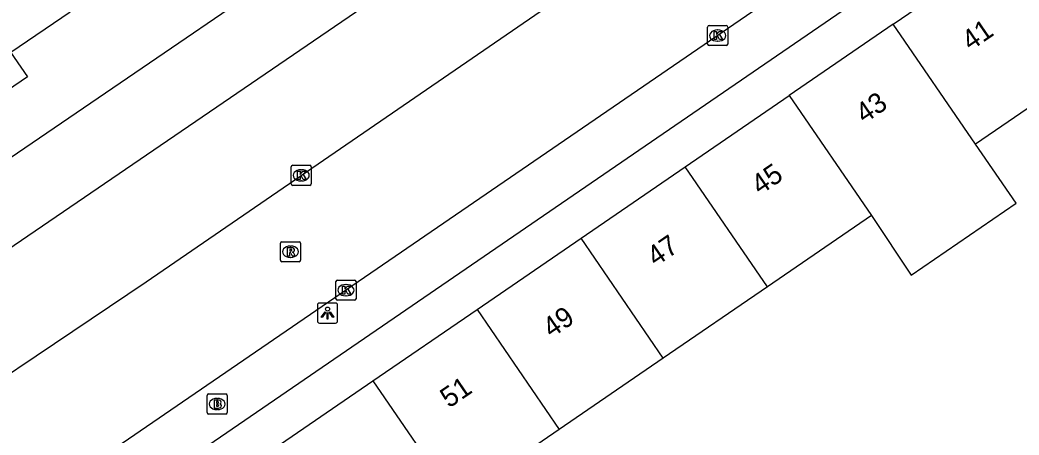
# Model space of a CAD drawing. Extents: x 157466 to 158888, y 383063 to 384677.
# Drawn here: x 158400.94 to 158450.69, y 383765.41 to 383786.08 of the extents above; entities that cross this region are included whole.
import ezdxf

# ---------------------------------------------------------------- set-up
doc = ezdxf.new("R2010")
doc.units = 0
for name, color, linetype in [('IMGEO_Brandkraan', 7, 'Continuous'), ('IMGEO_Kolk', 7, 'Continuous'), ('IMGEO_Lichtpunt', 7, 'Continuous'), ('IMGEO_Pand', 7, 'Continuous'), ('IMGEO_Pand_nummerreeks', 7, 'Continuous'), ('IMGEO_Rijbaan_lokaal_open', 7, 'Continuous'), ('IMGEO_Rioolput', 7, 'Continuous'), ('IMGEO_Voetpad_open', 7, 'Continuous')]:
    doc.layers.add(name, color=color, linetype=linetype)

msp = doc.modelspace()

# ---------------------------------------------------------------- linework, layer by layer
at = {"layer": 'IMGEO_Brandkraan'}
for p, q in [((158410.262, 383766.531), (158410.262, 383767.383)), ((158410.337, 383767.457), (158411.189, 383767.457)), ((158410.75, 383767.237), (158410.775, 383767.237)), ((158411.263, 383767.383), (158411.263, 383766.531)), ((158410.773, 383766.677), (158410.748, 383766.677)), ((158411.189, 383766.457), (158410.337, 383766.457))]:
    msp.add_line(p, q, dxfattribs=at)
for points in [[(158410.262, 383766.531), (158410.262, 383767.383)], [(158410.337, 383767.457), (158411.189, 383767.457)], [(158410.61, 383767.157), (158410.61, 383766.757), (158410.823, 383766.757)], [(158410.841, 383767.157), (158410.61, 383767.157)], [(158410.789, 383767.076), (158410.735, 383767.076), (158410.735, 383767)], [(158410.735, 383767), (158410.788, 383767)], [(158411.263, 383767.383), (158411.263, 383766.531)], [(158410.797, 383766.924), (158410.735, 383766.924), (158410.735, 383766.843)], [(158410.735, 383766.843), (158410.797, 383766.843)], [(158411.189, 383766.457), (158410.337, 383766.457)]]:
    msp.add_lwpolyline(points, dxfattribs=at)
for centre, radius, start, end in [((158410.339, 383767.381), 0.0765, 91.552, 178.448), ((158410.339, 383767.381), 0.0765, 91.552, 178.448), ((158410.79, 383767.038), 0.0379, 267.8285, 90.9355), ((158410.845, 383767.012), 0.145, 59.4692, 91.5367), ((158410.87, 383767.059), 0.0922, 285.5137, 58.1501), ((158411.187, 383767.381), 0.0765, 1.552, 88.448), ((158411.187, 383767.381), 0.0765, 1.552, 88.448), ((158410.339, 383766.533), 0.0765, 181.552, 268.448), ((158410.339, 383766.533), 0.0765, 181.552, 268.448), ((158410.798, 383766.883), 0.0404, 269.8759, 90.5077), ((158410.829, 383767.008), 0.251, 268.6676, 293.5347), ((158410.875, 383766.867), 0.105, 301.3115, 78.989), ((158411.187, 383766.533), 0.0765, 271.552, 358.448), ((158411.187, 383766.533), 0.0765, 271.552, 358.448)]:
    msp.add_arc(centre, radius, start, end, dxfattribs=at)
for centre, major_axis, ratio, start_param, end_param in [((158410.749, 383766.957), (-0.387, 0.002), 0.722429, 4.712389, 7.853982), ((158410.774, 383766.957), (-0.39, 0.002), 0.717154, 1.570796, 4.712389)]:
    msp.add_ellipse(centre, major_axis=major_axis, ratio=ratio, start_param=start_param, end_param=end_param, dxfattribs=at)
at = {"layer": 'IMGEO_Kolk'}
for p, q in [((158435.185, 383784.881), (158435.185, 383785.733)), ((158435.26, 383785.807), (158436.112, 383785.807)), ((158435.673, 383785.587), (158435.698, 383785.587)), ((158436.186, 383785.733), (158436.186, 383784.881)), ((158435.696, 383785.027), (158435.671, 383785.027)), ((158436.112, 383784.807), (158435.26, 383784.807)), ((158414.448, 383777.92), (158414.448, 383778.772)), ((158414.523, 383778.846), (158415.375, 383778.846)), ((158414.936, 383778.626), (158414.961, 383778.626)), ((158415.449, 383778.772), (158415.449, 383777.92)), ((158414.959, 383778.066), (158414.934, 383778.066)), ((158415.375, 383777.846), (158414.523, 383777.846)), ((158416.676, 383772.202), (158416.676, 383773.054)), ((158416.751, 383773.128), (158417.603, 383773.128)), ((158417.677, 383773.054), (158417.677, 383772.202)), ((158417.164, 383772.908), (158417.189, 383772.908)), ((158417.603, 383772.128), (158416.751, 383772.128)), ((158417.187, 383772.348), (158417.162, 383772.348))]:
    msp.add_line(p, q, dxfattribs=at)
for points in [[(158435.185, 383784.881), (158435.185, 383785.733)], [(158435.26, 383785.807), (158436.112, 383785.807)], [(158435.506, 383785.507), (158435.629, 383785.507), (158435.629, 383785.356), (158435.759, 383785.507), (158435.923, 383785.507), (158435.777, 383785.356), (158435.93, 383785.107), (158435.778, 383785.107), (158435.693, 383785.271), (158435.629, 383785.204), (158435.629, 383785.107), (158435.506, 383785.107), (158435.506, 383785.507)], [(158436.186, 383785.733), (158436.186, 383784.881)], [(158436.112, 383784.807), (158435.26, 383784.807)], [(158414.448, 383777.92), (158414.448, 383778.772)], [(158414.523, 383778.846), (158415.375, 383778.846)], [(158414.769, 383778.546), (158414.892, 383778.546), (158414.892, 383778.395), (158415.022, 383778.546), (158415.186, 383778.546), (158415.04, 383778.395), (158415.193, 383778.146), (158415.041, 383778.146), (158414.956, 383778.31), (158414.892, 383778.243), (158414.892, 383778.146), (158414.769, 383778.146), (158414.769, 383778.546)], [(158415.449, 383778.772), (158415.449, 383777.92)], [(158415.375, 383777.846), (158414.523, 383777.846)], [(158416.676, 383772.202), (158416.676, 383773.054)], [(158416.751, 383773.128), (158417.603, 383773.128)], [(158417.677, 383773.054), (158417.677, 383772.202)], [(158416.997, 383772.828), (158417.12, 383772.828), (158417.12, 383772.677), (158417.25, 383772.828), (158417.414, 383772.828), (158417.268, 383772.677), (158417.421, 383772.428), (158417.269, 383772.428), (158417.184, 383772.592), (158417.12, 383772.525), (158417.12, 383772.428), (158416.997, 383772.428), (158416.997, 383772.828)], [(158417.603, 383772.128), (158416.751, 383772.128)]]:
    msp.add_lwpolyline(points, dxfattribs=at)
for centre, start, end in [((158435.262, 383785.731), 91.552, 178.448), ((158435.262, 383785.731), 91.552, 178.448), ((158436.11, 383785.731), 1.552, 88.448), ((158436.11, 383785.731), 1.552, 88.448), ((158435.262, 383784.883), 181.552, 268.448), ((158435.262, 383784.883), 181.552, 268.448), ((158436.11, 383784.883), 271.552, 358.448), ((158436.11, 383784.883), 271.552, 358.448), ((158414.525, 383778.77), 91.552, 178.448), ((158414.525, 383778.77), 91.552, 178.448), ((158415.373, 383778.77), 1.552, 88.448), ((158415.373, 383778.77), 1.552, 88.448), ((158414.525, 383777.922), 181.552, 268.448), ((158414.525, 383777.922), 181.552, 268.448), ((158415.373, 383777.922), 271.552, 358.448), ((158415.373, 383777.922), 271.552, 358.448), ((158416.753, 383773.052), 91.552, 178.448), ((158416.753, 383773.052), 91.552, 178.448), ((158417.601, 383773.052), 1.552, 88.448), ((158417.601, 383773.052), 1.552, 88.448), ((158416.753, 383772.204), 181.552, 268.448), ((158416.753, 383772.204), 181.552, 268.448), ((158417.601, 383772.204), 271.552, 358.448), ((158417.601, 383772.204), 271.552, 358.448)]:
    msp.add_arc(centre, 0.0765, start, end, dxfattribs=at)
for centre, major_axis, ratio, start_param, end_param in [((158435.672, 383785.307), (-0.387, 0.002), 0.722429, 4.712389, 7.853982), ((158435.697, 383785.307), (-0.39, 0.002), 0.717154, 1.570796, 4.712389), ((158414.935, 383778.346), (-0.387, 0.002), 0.722429, 4.712389, 7.853982), ((158414.96, 383778.346), (-0.39, 0.002), 0.717154, 1.570796, 4.712389), ((158417.163, 383772.628), (-0.387, 0.002), 0.722429, 4.712389, 7.853982), ((158417.188, 383772.628), (-0.39, 0.002), 0.717154, 1.570796, 4.712389)]:
    msp.add_ellipse(centre, major_axis=major_axis, ratio=ratio, start_param=start_param, end_param=end_param, dxfattribs=at)
at = {"layer": 'IMGEO_Lichtpunt'}
for p, q in [((158416.661, 383771.984), (158415.853, 383771.984)), ((158416.661, 383771.984), (158415.853, 383771.984)), ((158415.759, 383771.889), (158415.759, 383771.082)), ((158415.759, 383771.889), (158415.759, 383771.082)), ((158416.755, 383771.082), (158416.755, 383771.889)), ((158416.755, 383771.082), (158416.755, 383771.889)), ((158415.853, 383770.988), (158416.661, 383770.988)), ((158415.853, 383770.988), (158416.661, 383770.988))]:
    msp.add_line(p, q, dxfattribs=at)
for points in [[(158416.133, 383771.553), (158416.172, 383771.525), (158415.984, 383771.263), (158415.946, 383771.29), (158416.133, 383771.553)], [(158416.235, 383771.505), (158416.282, 383771.505), (158416.282, 383771.183), (158416.235, 383771.183), (158416.235, 383771.505)], [(158416.345, 383771.525), (158416.383, 383771.552), (158416.57, 383771.29), (158416.531, 383771.262), (158416.345, 383771.525)]]:
    msp.add_lwpolyline(points, dxfattribs=at)
msp.add_circle((158416.258, 383771.687), 0.0994, dxfattribs=at)
for centre, start, end in [((158415.853, 383771.889), 90, 180), ((158415.853, 383771.889), 90, 180), ((158416.661, 383771.889), 0, 90), ((158416.661, 383771.889), 0, 90), ((158415.853, 383771.082), 180, 270), ((158415.853, 383771.082), 180, 270), ((158416.661, 383771.082), 270, 0), ((158416.661, 383771.082), 270, 360)]:
    msp.add_arc(centre, 0.0946, start, end, dxfattribs=at)
at = {"layer": 'IMGEO_Pand'}
for points in [[(158442.619, 383817.275), (158437.202, 383813.58), (158439.887, 383809.644), (158428.548, 383801.911), (158426.177, 383805.388), (158423.704, 383803.702), (158424.427, 383802.642), (158402.712, 383787.832), (158402.577, 383787.74), (158403.44, 383786.474), (158400.485, 383784.46), (158400.653, 383784.214), (158401.312, 383783.247), (158389.931, 383775.485), (158388.503, 383777.577), (158386.41, 383776.149), (158383.749, 383780.051)], [(158444.429, 383785.881), (158449.611, 383789.434)], [(158444.429, 383785.881), (158439.247, 383782.328)], [(158448.528, 383779.899), (158444.429, 383785.881)], [(158453.711, 383783.45), (158448.528, 383779.899)], [(158434.066, 383778.775), (158439.247, 383782.328)], [(158439.247, 383782.328), (158443.345, 383776.348)], [(158443.345, 383776.348), (158445.315, 383773.373), (158450.544, 383776.956), (158448.528, 383779.899)], [(158428.883, 383775.222), (158434.066, 383778.775)], [(158438.162, 383772.796), (158434.066, 383778.775)], [(158443.345, 383776.348), (158438.162, 383772.796)], [(158423.702, 383771.669), (158428.883, 383775.222)], [(158432.979, 383769.245), (158428.883, 383775.222)], [(158438.162, 383772.796), (158432.979, 383769.245)], [(158418.52, 383768.116), (158423.702, 383771.669)], [(158423.702, 383771.669), (158427.796, 383765.693)], [(158432.979, 383769.245), (158427.796, 383765.693)], [(158413.338, 383764.563), (158418.52, 383768.116)], [(158418.52, 383768.116), (158422.613, 383762.142)], [(158427.796, 383765.693), (158422.613, 383762.142)]]:
    msp.add_lwpolyline(points, dxfattribs=at)
at = {"layer": 'IMGEO_Rijbaan_lokaal_open'}
for points in [[(158394.384, 383764.411), (158407.233, 383773.047), (158444.242, 383798.459)], [(158447.639, 383793.508), (158438.021, 383786.908), (158394.268, 383756.934)]]:
    msp.add_lwpolyline(points, dxfattribs=at)
at = {"layer": 'IMGEO_Rioolput'}
for p, q in [((158413.915, 383774.116), (158413.915, 383774.968)), ((158413.99, 383775.042), (158414.842, 383775.042)), ((158414.916, 383774.968), (158414.916, 383774.116)), ((158414.403, 383774.822), (158414.428, 383774.822)), ((158414.842, 383774.042), (158413.99, 383774.042)), ((158414.426, 383774.262), (158414.401, 383774.262))]:
    msp.add_line(p, q, dxfattribs=at)
for points in [[(158413.915, 383774.116), (158413.915, 383774.968)], [(158413.99, 383775.042), (158414.842, 383775.042)], [(158414.916, 383774.968), (158414.916, 383774.116)], [(158414.504, 383774.74), (158414.252, 383774.742), (158414.252, 383774.342)], [(158414.252, 383774.342), (158414.376, 383774.342), (158414.376, 383774.504), (158414.387, 383774.504)], [(158414.43, 383774.661), (158414.376, 383774.661), (158414.376, 383774.58)], [(158414.376, 383774.58), (158414.428, 383774.58)], [(158414.434, 383774.475), (158414.505, 383774.342), (158414.645, 383774.342), (158414.58, 383774.468)], [(158414.842, 383774.042), (158413.99, 383774.042)]]:
    msp.add_lwpolyline(points, dxfattribs=at)
for centre, radius, start, end in [((158413.992, 383774.966), 0.0765, 91.552, 178.448), ((158413.992, 383774.966), 0.0765, 91.552, 178.448), ((158414.84, 383774.966), 0.0765, 1.552, 88.448), ((158414.84, 383774.966), 0.0765, 1.552, 88.448), ((158414.386, 383774.451), 0.0533, 26.0293, 88.6989), ((158414.412, 383774.769), 0.19, 274.7715, 282.9687), ((158414.436, 383774.565), 0.0964, 77.0061, 93.1865), ((158414.45, 383774.622), 0.0378, 276.6634, 79.6772), ((158414.503, 383774.63), 0.109, 350.3612, 89.416), ((158414.501, 383774.63), 0.112, 277.5842, 350.9817), ((158414.485, 383774.415), 0.108, 29.5134, 73.7905), ((158413.992, 383774.118), 0.0765, 181.552, 268.448), ((158413.992, 383774.118), 0.0765, 181.552, 268.448), ((158414.84, 383774.118), 0.0765, 271.552, 358.448), ((158414.84, 383774.118), 0.0765, 271.552, 358.448)]:
    msp.add_arc(centre, radius, start, end, dxfattribs=at)
for centre, major_axis, ratio, start_param, end_param in [((158414.402, 383774.542), (-0.387, 0.002), 0.722429, 4.712389, 7.853982), ((158414.427, 383774.542), (-0.39, 0.002), 0.717154, 1.570796, 4.712389)]:
    msp.add_ellipse(centre, major_axis=major_axis, ratio=ratio, start_param=start_param, end_param=end_param, dxfattribs=at)
at = {"layer": 'IMGEO_Voetpad_open'}
for points in [[(158512.351, 383834.835), (158500, 383826.37), (158395.719, 383754.902)], [(158442.667, 383807.999), (158390.257, 383772.256)], [(158392.331, 383769.184), (158440.564, 383802.129)]]:
    msp.add_lwpolyline(points, dxfattribs=at)

# ---------------------------------------------------------------- texts
at = {"layer": 'IMGEO_Pand_nummerreeks'}
for s, rotation, p in [('41', 34.4213, (158448.276, 383784.522)), ('43', 34.4233, (158442.99, 383780.899)), ('45', 34.4213, (158437.796, 383777.34)), ('47', 34.4213, (158432.602, 383773.78)), ('49', 34.4213, (158427.408, 383770.221)), ('51', 34.4213, (158422.307, 383766.726))]:
    msp.add_text(s, height=1, rotation=rotation, dxfattribs=at).set_placement(p)

doc.saveas('drawing.dxf')
